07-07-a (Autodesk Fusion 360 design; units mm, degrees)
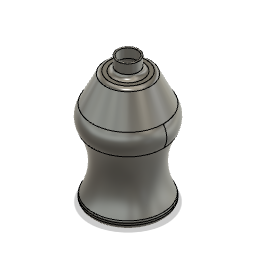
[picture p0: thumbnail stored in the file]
sketch "スケッチ1" plane through (0, 0, 0) normal (0, 1, 0) x axis (1, 0, 0)
  circle C1 centre (0, 0) radius 25
  point P1 (0, 0)
  point P2 (0, 0)
  coincident P1 P2
  dimension "d1" diameter C1 = 50
extrude "押し出し1" new body sketch "スケッチ1" along normal blind 5
work_plane "作業平面1" AlongDistance 20
sketch "スケッチ2" plane through (0, 25, 0) normal (0, 1, 0) x axis (1, 0, 0)
  circle C1 centre (0, 0) radius 20
  point P1 (0, 0)
  point P2 (0, 0)
  coincident P1 P2
  dimension "d5" diameter C1 = 40
work_plane "作業平面2" AlongDistance 20
sketch "スケッチ3" plane through (0, 45, 0) normal (0, 1, 0) x axis (1, 0, 0)
  circle C1 centre (0, 0) radius 25
loft "ロフト1" sketch "スケッチ2" + "スケッチ3"
work_plane "作業平面3" AlongDistance 15
sketch "スケッチ4" plane through (0, 60, 0) normal (0, 1, 0) x axis (1, 0, 0)
  circle C1 centre (0, 0) radius 25
sketch "スケッチ5" plane through (0, 0, 0) normal (0, 0, 1) x axis (1, 0, 0)
  line L1 (-25, 60) -> (25, 60)
  line L2 (25, 45) -> (-25, 45)
  arc A1 centre (-14.3816, 52.5) radius 13 clockwise from (-25, 45) to (-25, 60)
  arc A2 centre (14.3816, 52.5) radius 13 clockwise from (25, 60) to (25, 45)
  point P2 (-25, 60)
  point P9 (-25, 60)
  point P3 (-25, 45)
  point P10 (-25, 45)
  point P5 (25, 60)
  point P8 (25, 60)
  point P6 (25, 45)
  point P11 (25, 45)
  coincident P2 P9
  coincident P3 P10
  coincident P5 P8
  coincident P6 P11
  equal A1 A2
  dimension "d8" radius A1 = 13
sketch "スケッチ6" plane through (0, 0, 0) normal (1, 0, 0) x axis (0, 0, -1)
  line L1 (-25, 60) -> (25, 60)
  line L2 (25, 45) -> (-25, 45)
  arc A1 centre (-14.3816, 52.5) radius 13 clockwise from (-25, 45) to (-25, 60)
  arc A2 centre (14.3816, 52.5) radius 13 clockwise from (25, 60) to (25, 45)
  point P2 (-25, 60)
  point P9 (-25, 60)
  point P3 (-25, 45)
  point P10 (-25, 45)
  point P6 (25, 45)
  point P11 (25, 45)
  point P5 (25, 60)
  point P8 (25, 60)
  coincident P2 P9
  coincident P3 P10
  coincident P6 P11
  coincident P5 P8
  equal A1 A2
  dimension "d9" radius A1 = 13
loft "ロフト2" sketch "スケッチ4"
work_plane "作業平面4" AlongDistance 20
sketch "スケッチ7" plane through (0, 80, 0) normal (0, 1, 0) x axis (1, 0, 0)
  circle C1 centre (0, 0) radius 15
  point P1 (0, 0)
  point P2 (0, 0)
  coincident P1 P2
  dimension "d12" diameter C1 = 30
loft "ロフト3" sketch "スケッチ7"
sketch "スケッチ8" plane through (0, 80, 0) normal (0, 1, 0) x axis (-1, 0, 0)
  circle C1 centre (0, 0) radius 15
  circle C2 centre (0, 0) radius 7.5
  point P1 (0, 0)
  point P3 (0, 0)
  coincident P1 P3
  dimension "d13" diameter C2 = 15
extrude "押し出し2" add sketch "スケッチ8" profile of C2 along normal blind 10
fillet "フィレット1" radius 3
shell "シェル" innerThickness 1
fillet "フィレット2" radius 0.5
